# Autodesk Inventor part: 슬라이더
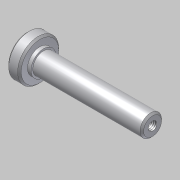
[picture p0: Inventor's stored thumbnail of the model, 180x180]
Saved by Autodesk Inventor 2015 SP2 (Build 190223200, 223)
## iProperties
Created: 2011-04
Part Number: 슬라이더
Document SubType Name: Modeling
Designer: 한국산업디자인학원 [http://gmhk.co.kr]
Density: 1 g/cm^3
Material: 일반
Appearance: 기본값
Mass: 9.77098 g
Surface Area: 38.1769 cm^2
Volume: 9.77098 cm^3
Author: pww
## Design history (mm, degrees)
sketch "스케치1"
  geometry: L1 (-7, 0)-(63, 0); L2 (63, 0)-(63, 6); L3 (63, 6)-(0, 6); L4 (-7, 0)-(-7, 11.5); L5 (-7, 11.5)-(0, 11.5); L6 (0, 11.5)-(0, 6); 1 further point
  constraints: 12 end point, 3 perpendicular, 2 horizontal, 2 point on line, 1 parallel
  dimensions: "d1" = 70 distance of L1.start L1.end; "d19" = 12 diameter of L3 L1; "d20" = 7 distance of L4.end L5.end; "d21" = 23 diameter of L5 L1
revolve "회전1" stored, may be unused: angle "d4" = 90 deg
chamfer "모따기1" distance "d16" = 1; stored, may be unused: second distance "d17" = 2, angle "d18" = 45 deg
hole "구멍2" diameter "d24" = 4.917; stored, may be unused: countersink angle "d28" = 90 deg, drill point angle "d30" = 118 deg; dims "d22" = 10, "d23" = 10, "d25" = 10, "d26" = 4, "d27" = 2, "d29" = 13
sketch "스케치2"
  geometry: C1 r 7 at (0, 0); 1 further point
  constraints: 1 centre point, 1 coincident
  dimensions: "d31" = 14 diameter of C1
extrude "돌출2" join sketch "스케치2" distance "d32" = 2; taper "d33" = 0 deg
node "솔리드1"
